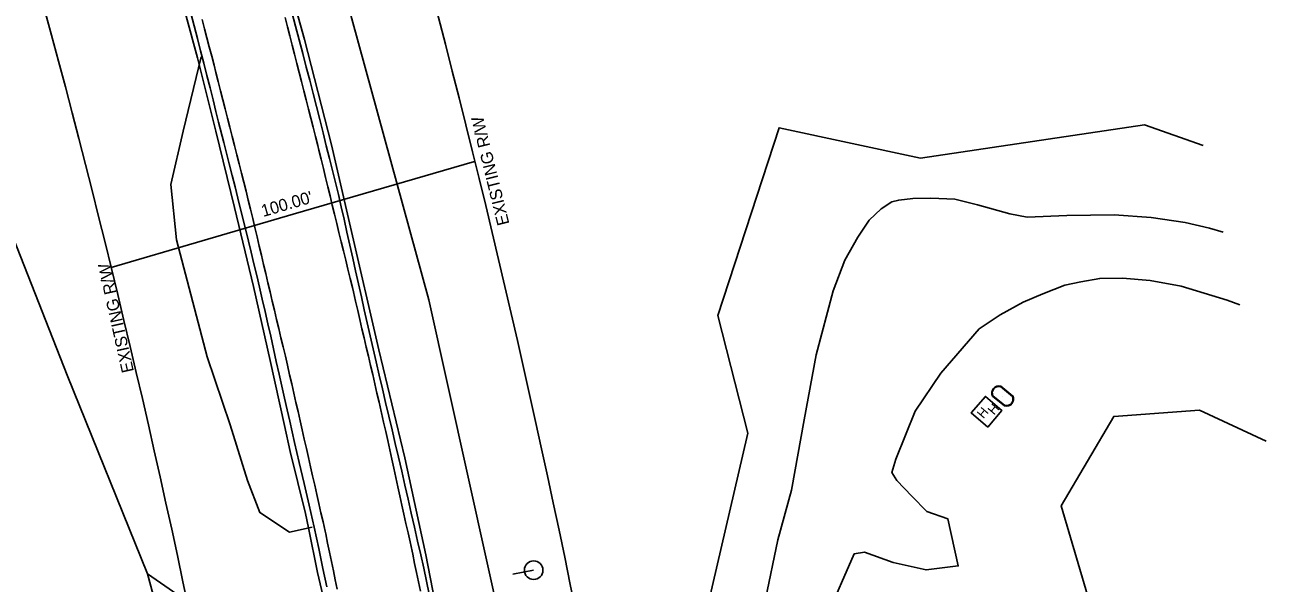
# Model space of a CAD drawing. Extents: x 472260 to 482161, y 489063 to 507124.
# Drawn here: x 477871.1 to 478199, y 498795.2 to 498942.7 of the extents above; entities that cross this region are included whole.
import ezdxf

# ---------------------------------------------------------------- set-up
doc = ezdxf.new("R2010")
doc.units = 0
for name, color, linetype in [('Exist Structure Minor Drop Inlet Cogo Elevation', 7, 'Continuous'), ('Exist Structure Minor Pipes CMP 15 Inch Cogo Comment', 7, 'Continuous'), ('Exist Structure Minor Pipes CMP 15 Inch Cogo Point CELL', 7, 'Continuous'), ('Prop Drainage Structure Catch Basin Convert From Junction Box Label', 7, 'Continuous'), ('Prop Drainage Structure Drop Inlet Grate 2 Narrow Slots and Sag Grates 840 24 CELL', 7, 'Continuous'), ('Prop Drainage Structure Pipe RCP 18in Class III', 7, 'Continuous'), ('Prop Drainage Structure Pipe Stub Out CELL', 7, 'Continuous'), ('Prop Drainage Structure Tops and Inverts LABEL', 7, 'Continuous'), ('Prop Erosion Rip Rap Pad at Outlet Label', 7, 'Continuous'), ('Prop NEU Channel Block Detail Label', 7, 'Continuous'), ('Prop Plan Preparation Excavation Hatching', 7, 'Continuous'), ('Prop Roadway Culvert', 7, 'Continuous')]:
    doc.layers.add(name, color=color, linetype=linetype)

msp = doc.modelspace()

# ---------------------------------------------------------------- linework, layer by layer
at = {"layer": 'Exist Structure Minor Drop Inlet Cogo Elevation'}
for radius in [2924.21, 2824.21]:
    msp.add_arc((475150.42, 498208.04), radius, 10.42705, 28.78535, dxfattribs=at)
at = {"layer": 'Exist Structure Minor Pipes CMP 15 Inch Cogo Comment'}
for p in [(477989.88, 498906.59), (477893.87, 498878.62)]:
    msp.add_line(p, (477941.96, 498892.63), dxfattribs=at)
at = {"layer": 'Prop Drainage Structure Catch Basin Convert From Junction Box Label'}
for points in [[(477996.51, 498701.33), (477993.74, 498716.69), (477990.46, 498733.83), (477985.88, 498758.04), (477983.51, 498769.13), (477976.97, 498802.63), (477971.47, 498828.29), (477964.59, 498856.8), (477957.12, 498889.21), (477952.05, 498910.97), (477944.91, 498938.83), (477937.4, 498966.04), (477929.86, 498994.18), (477923.48, 499016.53), (477918.46, 499033.05)], [(477968.51, 498697.7), (477964.57, 498719.96), (477960.6, 498739.33), (477957.08, 498757.49), (477954, 498771.52), (477950.47, 498789.03), (477948.35, 498797.99), (477945.98, 498809.81), (477945.17, 498813.58), (477941.18, 498829.97), (477939.67, 498836.85), (477935.83, 498854), (477931.51, 498873.52), (477926.45, 498894.44), (477921.49, 498914.61), (477916.72, 498933.94), (477910.94, 498955.11)]]:
    msp.add_lwpolyline(points, dxfattribs=at)
at = {"layer": 'Prop Drainage Structure Drop Inlet Grate 2 Narrow Slots and Sag Grates 840 24 CELL'}
for points in [[(477953.57, 498793.59), (477953.07, 498796.03), (477952.56, 498798.47), (477952.06, 498800.91), (477951.55, 498803.35), (477951.05, 498805.79), (477950.54, 498808.23), (477950.4, 498808.93), (477949.84, 498811.36), (477949.29, 498813.79), (477948.74, 498816.22), (477948.19, 498818.65), (477947.64, 498821.08), (477947.09, 498823.51), (477946.54, 498825.94), (477945.99, 498828.37), (477945.43, 498830.8), (477944.88, 498833.23), (477944.33, 498835.66), (477943.78, 498838.09), (477943.23, 498840.52), (477942.68, 498842.95), (477942.13, 498845.38), (477941.58, 498847.81), (477941.02, 498850.23), (477940.46, 498852.74), (477939.88, 498855.16), (477939.31, 498857.59), (477938.73, 498860.01), (477938.16, 498862.44), (477937.58, 498864.86), (477937, 498867.29), (477936.43, 498869.71), (477935.85, 498872.14), (477935.28, 498874.56), (477934.7, 498876.99), (477934.13, 498879.41), (477933.55, 498881.84), (477932.98, 498884.26), (477932.4, 498886.68), (477931.83, 498889.11), (477931.25, 498891.53), (477930.68, 498893.96), (477930.1, 498896.38), (477929.55, 498898.71), (477928.93, 498901.13), (477928.32, 498903.54), (477927.7, 498905.96), (477927.09, 498908.38), (477926.48, 498910.79), (477925.86, 498913.21), (477925.25, 498915.62), (477924.63, 498918.04), (477924.02, 498920.46), (477923.4, 498922.87), (477922.79, 498925.29), (477922.17, 498927.7), (477921.56, 498930.12), (477921.07, 498932.03), (477920.44, 498934.44), (477919.8, 498936.85), (477919.17, 498939.26), (477918.54, 498941.67), (477917.9, 498944.08)], [(477975.56, 498793.09), (477975.05, 498795.52), (477974.54, 498797.96), (477974.03, 498800.4), (477973.52, 498802.84), (477973.35, 498803.64), (477972.82, 498806.07), (477972.28, 498808.5), (477971.75, 498810.94), (477971.21, 498813.37), (477970.68, 498815.81), (477970.14, 498818.24), (477969.6, 498820.67), (477969.07, 498823.11), (477968.53, 498825.54), (477968, 498827.98), (477967.46, 498830.41), (477966.92, 498832.84), (477966.39, 498835.28), (477965.85, 498837.71), (477965.32, 498840.15), (477965.23, 498840.56), (477964.66, 498842.98), (477964.09, 498845.41), (477963.53, 498847.84), (477962.96, 498850.27), (477962.39, 498852.69), (477961.82, 498855.12), (477961.26, 498857.55), (477960.69, 498859.97), (477960.12, 498862.4), (477959.56, 498864.83), (477958.99, 498867.25), (477958.42, 498869.68), (477957.86, 498872.11), (477957.58, 498873.27), (477957, 498875.69), (477956.41, 498878.12), (477955.82, 498880.54), (477955.23, 498882.96), (477954.64, 498885.38), (477954.05, 498887.8), (477953.46, 498890.22), (477952.88, 498892.64), (477952.29, 498895.06), (477951.7, 498897.49), (477951.11, 498899.91), (477950.52, 498902.33), (477949.93, 498904.75), (477949.34, 498907.17), (477948.76, 498909.59), (477948.46, 498910.79), (477947.85, 498913.21), (477947.23, 498915.62), (477946.61, 498918.04), (477945.99, 498920.45), (477945.38, 498922.86), (477944.76, 498925.28), (477944.14, 498927.69), (477943.52, 498930.11), (477942.91, 498932.52), (477942.29, 498934.94), (477941.67, 498937.35), (477941.05, 498939.77), (477940.44, 498942.18), (477939.82, 498944.59)]]:
    msp.add_lwpolyline(points, dxfattribs=at)
at = {"layer": 'Prop Drainage Structure Pipe RCP 18in Class III'}
for points in [[(477946.96, 498810.01), (477940.97, 498808.62), (477933.11, 498813.85), (477929.86, 498822.29), (477925.33, 498837), (477919.23, 498854.95), (477911.11, 498885.89), (477909.62, 498900.51), (477912.88, 498914.64), (477917.69, 498934.2)], [(478066.75, 498790.95), (478070.01, 498806.62), (478073.56, 498819.77), (478076.93, 498838.36), (478080.08, 498855.54), (478084.56, 498872.46), (478087.7, 498880.52), (478091.07, 498886.6), (478094.12, 498891.05), (478097.25, 498894.05), (478100.09, 498895.97), (478101.9, 498896.41), (478105.6, 498896.8), (478110.38, 498896.94), (478116.74, 498896.61), (478122.68, 498895.17), (478131.22, 498892.78), (478135.86, 498891.84), (478146.28, 498892.29), (478158.83, 498892.47), (478168.6, 498891.75), (478177.52, 498890.43), (478184, 498889.01), (478187.63, 498887.9)], [(478192, 498868.68), (478188.62, 498869.98), (478176.51, 498873.68), (478168.31, 498875.11), (478160.97, 498875.8), (478154.98, 498875.68), (478150.03, 498874.79), (478145.8, 498873.88), (478140, 498871.6), (478134.77, 498869.38), (478128.71, 498866.06), (478123.16, 498862.38), (478113.02, 498850.7), (478106.2, 498840.61), (478101.18, 498827.95), (478100.11, 498824.41), (478101.42, 498822.29), (478105.39, 498818.19), (478109.32, 498814.08), (478114.84, 498812.2), (478117.63, 498799.76), (478109.13, 498798.68), (478100.46, 498800.61), (478092.87, 498803.38), (478090.11, 498802.9), (478082.8, 498786.24)]]:
    msp.add_lwpolyline(points, dxfattribs=at)
at = {"layer": 'Prop Drainage Structure Pipe Stub Out CELL'}
for points in [[(477977.84, 498792.26), (477977.15, 498795.67), (477976.42, 498799.15), (477975.63, 498802.7), (477974.81, 498806.31), (477973.99, 498809.96), (477973.15, 498813.64), (477972.31, 498817.37), (477971.47, 498821.09), (477970.62, 498824.78), (477969.78, 498828.44), (477968.93, 498832.06), (477968.08, 498835.67), (477967.23, 498839.28), (477966.38, 498842.89), (477965.52, 498846.51), (477964.67, 498850.1), (477963.85, 498853.64), (477963.05, 498857.13), (477962.27, 498860.57), (477961.5, 498863.99), (477960.73, 498867.4), (477959.96, 498870.83), (477959.2, 498874.25), (477958.43, 498877.67), (477957.67, 498881.09), (477956.91, 498884.51), (477956.15, 498887.93), (477955.39, 498891.31), (477954.64, 498894.61), (477953.88, 498897.85), (477953.11, 498901.01), (477952.34, 498904.17), (477951.53, 498907.42), (477950.7, 498910.76), (477949.83, 498914.19), (477948.95, 498917.65), (477948.07, 498921.12), (477947.19, 498924.59), (477946.31, 498928.06), (477945.42, 498931.55), (477944.5, 498935.1), (477943.56, 498938.7), (477942.59, 498942.35), (477941.59, 498946.06)], [(477950.83, 498794.22), (477949.79, 498799.08), (477948.69, 498804.31), (477947.48, 498809.97), (477946.19, 498815.75), (477944.83, 498821.54), (477943.54, 498827.05), (477942.31, 498832.33), (477941.03, 498837.96), (477940.36, 498840.94), (477939.67, 498844.02), (477938.96, 498847.19), (477938.24, 498850.44), (477937.5, 498853.77), (477936.75, 498857.12), (477936.01, 498860.44), (477935.26, 498863.72), (477934.52, 498866.97), (477933.78, 498870.18), (477933.04, 498873.35), (477932.31, 498876.47), (477931.58, 498879.56), (477930.86, 498882.59), (477929.44, 498888.42), (477928.05, 498894.02), (477927.33, 498896.91), (477926.59, 498899.87), (477925.83, 498902.92), (477925.07, 498905.94), (477923.64, 498911.64), (477922.26, 498916.99), (477921.54, 498919.84), (477920.78, 498922.85), (477919.99, 498926.02), (477919.18, 498929.28), (477918.35, 498932.54), (477917.51, 498935.82), (477916.65, 498939.1), (477915.78, 498942.41), (477914.89, 498945.77)]]:
    msp.add_lwpolyline(points, dxfattribs=at)
at = {"layer": 'Prop Drainage Structure Tops and Inverts LABEL'}
msp.add_lwpolyline([(477903.45, 498797.63), (477916.96, 498788.32), (477931.12, 498784.97), (477945.58, 498759.61), (477955.28, 498734.27), (477961.94, 498706.58)], dxfattribs=at)
at = {"layer": 'Prop Erosion Rip Rap Pad at Outlet Label'}
for points in [[(478182.3, 498910.77), (478166.83, 498916.31), (478107.63, 498907.49), (478070.29, 498915.49), (478054.1, 498865.86), (478062.04, 498834.83), (478043.51, 498754.74), (478021.79, 498715.6), (478012.98, 498719.06), (477998.42, 498777.13), (477977.8, 498870.01), (477942.42, 498999.34), (477929.03, 499039.05), (477877.26, 499206.51)], [(477771.36, 499171.02), (477801.04, 499098.02), (477836.35, 499006.26), (477847.24, 498939.21), (477882.23, 498850.13), (477903.45, 498797.63), (477909.74, 498774.45), (477889.45, 498735.82), (477899.46, 498701.89)], [(478096.71, 498735.02), (478118.76, 498755.05), (478133.15, 498771.21), (478149.79, 498766.93), (478157.42, 498772.89), (478144.82, 498815.57), (478158.68, 498839.22), (478181.38, 498840.88), (478198.96, 498832.66)]]:
    msp.add_lwpolyline(points, dxfattribs=at)
at = {"layer": 'Prop NEU Channel Block Detail Label'}
for q in [(477999.94, 498797.58), (478005.47, 498798.61)]:
    msp.add_line((478005.47, 498798.61), q, dxfattribs=at)
msp.add_circle((478005.47, 498798.61), 2.45, dxfattribs=at)
at = {"layer": 'Prop Plan Preparation Excavation Hatching'}
msp.add_line((478125.28, 498840.44), (478125.28, 498840.44), dxfattribs=at)
msp.add_lwpolyline([(478125.43, 498836.42), (478129.17, 498840.79), (478124.8, 498844.53), (478121.06, 498840.16), (478125.43, 498836.42)], dxfattribs=at)
at = {"layer": 'Prop Roadway Culvert'}
msp.add_line((478129.35, 498844.62), (478129.35, 498844.62), dxfattribs=at)
for points in [[(478129.85, 498842.02), (478126.7, 498844.6)], [(478129.93, 498842.12), (478126.78, 498844.71)], [(478128.76, 498847.12), (478131.93, 498844.52)], [(478128.85, 498847.23), (478132.02, 498844.63)]]:
    msp.add_lwpolyline(points, dxfattribs=at)
for centre, radius, start, end in [((478128.35, 498845.44), 1.86, 74.3025, 206.9626), ((478128.34, 498845.45), 1.73, 75.7814, 205.527), ((478130.36, 498843.8), 1.86, 253.8322, 26.6336), ((478130.35, 498843.81), 1.73, 255.9551, 24.4366)]:
    msp.add_arc(centre, radius, start, end, dxfattribs=at)

# ---------------------------------------------------------------- texts
at = {"layer": 'Exist Structure Minor Pipes CMP 15 Inch Cogo Comment'}
msp.add_text("100.00'", height=3.2, rotation=16.2407, dxfattribs=at).set_placement((477934.04, 498891.91))
at = {"layer": 'Exist Structure Minor Pipes CMP 15 Inch Cogo Point CELL'}
for rotation, p in [(103.8103, (477999.09, 498890.14)), (102.5551, (477899.9, 498851.17))]:
    msp.add_text('EXISTING R/W', height=3.2, rotation=rotation, dxfattribs=at).set_placement(p)
at = {"layer": 'Prop Plan Preparation Excavation Hatching'}
for p in [(478124.24, 498838.49), (478127.06, 498839.45)]:
    msp.add_text('H', height=2.5, rotation=49.4691, dxfattribs=at).set_placement(p)

doc.saveas('drawing.dxf')
